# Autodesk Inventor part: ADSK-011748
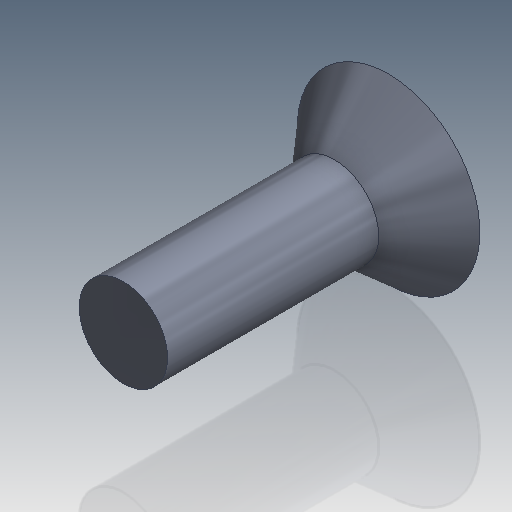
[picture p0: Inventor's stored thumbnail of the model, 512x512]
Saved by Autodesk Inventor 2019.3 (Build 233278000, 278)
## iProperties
Created: 2000-03
Part Number: ADSK-011748
Material: Pearson Stainless Steel
Document SubType Name: Modeling
Designer: sspink
Density: 8.03 g/cm^3
Appearance: Pearson-Stainless
Mass: 6.26897 g
Surface Area: 6.26461 cm^2
Volume: 0.780693 cm^3
Control State: 0
Master: False
Checked Out: False
Shininess: 57.0
Length Units: 11272
Angle Units: 11279
Time Units: 11290
Mass Units: 11286
Length Display Precision: 3
Angle Display Precision: 2
Compacted: True
Cutlength: 23.25
Material Desc: Material Description goes here
Material_Number: Pearson
Dimensions: 0,5x0,5x0,8 in
Mass: 0,014 lb
Density: 8.03
Volumn: 0.7806930880113931
Area: 6.264608242041026
PropertySet Name: Model Information
Author: sspink
Revision Number: -
Title: ADSK-011748
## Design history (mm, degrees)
node "Solide1"
  node "Extrusion1" dims "d1" = 15, "d2" = 0
  node "Revolution1" dims "d5" = 90 deg
sketch "Sketch1"
  geometry: C1 r 3 at (0, 0); 1 further point
  constraints: 1 centre point, 1 coincident
  dimensions: "d0" = 6 diameter of C1
sketch "Sketch2"
  geometry: L1 (-3, 0)-(3, 0) reference; L2 (-3, 0)-(-6.477, -4); L3 (-6.477, -4)-(0, -4); L4 (0, -4)-(0, 0); L5 (-3, 0)-(0, 0); L6 (0, -7.663)-(0, 18.777) reference
  constraints: 8 end point, 1 collinear, 1 parallel, 1 perpendicular
  dimensions: "d3" = 4 distance between parallel lines of L3 L1; "d4" = 41 deg angle of L4 L2
workaxis "Work Axis1"
chamfer "Fase1" distance "d6" = 0.5; stored, may be unused: second distance "d7" = 2, angle "d8" = 45 deg
feature "Gewinde1" dims "d9" = 14.5, "d10" = 0
node "Corps solides"
node "Corps surfaciques"
